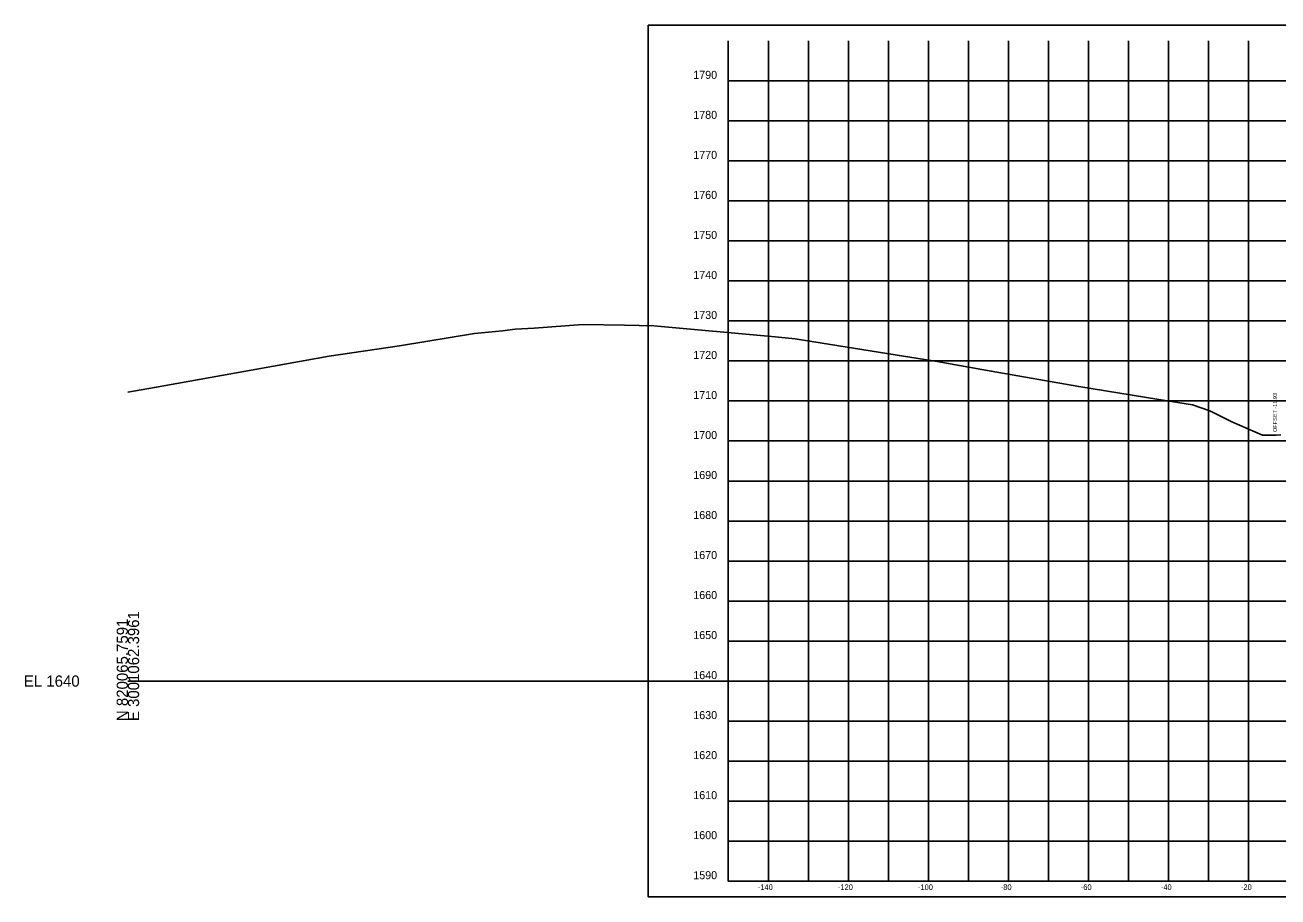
# Model space of a CAD drawing. Extents: x -26 to 603, y -61 to 1770.
# Drawn here: x -25.7 to 287.3, y 1446.1 to 1663.9 of the extents above; entities that cross this region are included whole.
import ezdxf

# ---------------------------------------------------------------- set-up
doc = ezdxf.new("R2010")
doc.units = 0
for name, color, linetype in [('DESIGN - SHEET - Corner Text', 7, 'Continuous'), ('DESIGN - SHEET - Light Grid', 7, 'Continuous'), ('DESIGN - SHEET - Linework', 7, 'Continuous'), ('DESIGN - SHEET - Plot Shape', 7, 'Continuous'), ('DESIGN - TYPICAL - Slope Tie Text', 7, 'Continuous'), ('SURVEY - GROUND - Top of Ground', 7, 'Continuous')]:
    doc.layers.add(name, color=color, linetype=linetype)

msp = doc.modelspace()

# ---------------------------------------------------------------- linework, layer by layer
at = {"layer": 'DESIGN - SHEET - Light Grid'}
msp.add_line((0, 1500), (300, 1500), dxfattribs=at)
at = {"layer": 'DESIGN - SHEET - Linework'}
for p, q in [((160, 1450), (160, 1660)), ((170, 1450), (170, 1660)), ((180, 1450), (180, 1660)), ((190, 1450), (190, 1660)), ((200, 1450), (200, 1660)), ((210, 1450), (210, 1660)), ((220, 1450), (220, 1660)), ((230, 1450), (230, 1660)), ((240, 1450), (240, 1660)), ((250, 1450), (250, 1660)), ((260, 1450), (260, 1660)), ((270, 1450), (270, 1660)), ((280, 1450), (280, 1660)), ((150, 1650), (450, 1650)), ((150, 1640), (450, 1640)), ((150, 1630), (450, 1630)), ((150, 1620), (450, 1620)), ((150, 1610), (450, 1610)), ((150, 1600), (450, 1600)), ((150, 1590), (450, 1590)), ((150, 1580), (450, 1580)), ((150, 1570), (450, 1570)), ((150, 1560), (450, 1560)), ((150, 1550), (450, 1550)), ((150, 1540), (450, 1540)), ((150, 1530), (450, 1530)), ((150, 1520), (450, 1520)), ((150, 1510), (450, 1510)), ((150, 1500), (450, 1500)), ((150, 1490), (450, 1490)), ((150, 1480), (450, 1480)), ((150, 1470), (450, 1470)), ((150, 1460), (450, 1460))]:
    msp.add_line(p, q, dxfattribs=at)
msp.add_lwpolyline([(150, 1660), (150, 1450), (450, 1450), (450, 1660)], dxfattribs=at)
at = {"layer": 'DESIGN - SHEET - Plot Shape'}
msp.add_lwpolyline([(130, 1663.94), (470, 1663.94), (470, 1446.06), (130, 1446.06)], close=True, dxfattribs=at)
at = {"layer": 'SURVEY - GROUND - Top of Ground'}
msp.add_lwpolyline([(0, 1572.22), (6.63, 1573.4), (28.94, 1577.36), (50.3, 1581.17), (67.86, 1583.81), (86.57, 1586.86), (93.56, 1587.55), (96.77, 1587.91), (101.47, 1588.18), (113.69, 1589.1), (124.1, 1588.93), (131.36, 1588.79), (161.7, 1585.99), (166.73, 1585.5), (192.17, 1581.46), (202.15, 1579.87), (215.69, 1577.49), (237.56, 1573.59), (257.54, 1570.4), (265.99, 1569.07), (270.3, 1567.51), (275.78, 1564.79), (283.42, 1561.44), (286.84, 1561.44), (288.07, 1561.5)], dxfattribs=at)

# ---------------------------------------------------------------- texts
at = {"layer": 'DESIGN - SHEET - Corner Text'}
for s, height, p in [('1790', 2, (141.25, 1650.5)), ('1780', 2, (141.25, 1640.5)), ('1770', 2, (141.25, 1630.5)), ('1760', 2, (141.25, 1620.5)), ('1750', 2, (141.25, 1610.5)), ('1740', 2, (141.25, 1600.5)), ('1730', 2, (141.25, 1590.5)), ('1720', 2, (141.25, 1580.5)), ('1710', 2, (141.25, 1570.5)), ('1700', 2, (141.25, 1560.5)), ('1690', 2, (141.25, 1550.5)), ('1680', 2, (141.25, 1540.5)), ('1670', 2, (141.25, 1530.5)), ('1660', 2, (141.25, 1520.5)), ('1650', 2, (141.25, 1510.5)), ('1640', 2, (141.25, 1500.5)), ('1630', 2, (141.25, 1490.5)), ('1620', 2, (141.25, 1480.5)), ('1610', 2, (141.25, 1470.5)), ('1600', 2, (141.25, 1460.5)), ('1590', 2, (141.25, 1450.5)), ('-140', 1.4, (157.37, 1447.8)), ('-120', 1.4, (177.37, 1447.8)), ('-100', 1.4, (197.37, 1447.8)), ('-80', 1.4, (218.06, 1447.8)), ('-60', 1.4, (238.06, 1447.8)), ('-40', 1.4, (258.06, 1447.8)), ('-20', 1.4, (278.06, 1447.8))]:
    msp.add_text(s, height=height, dxfattribs=at).set_placement(p)
at = {"layer": 'DESIGN - SHEET - Light Grid'}
for s, p in [('N 820065.7591', (0, 1490)), ('E 3001062.3961', (2.8, 1490))]:
    msp.add_text(s, height=2.8, rotation=90, dxfattribs=at).set_placement(p)
msp.add_text('EL 1640', height=2.8, dxfattribs=at).set_placement((-26, 1498.6))
at = {"layer": 'DESIGN - TYPICAL - Slope Tie Text'}
msp.add_text('OFFSET -11.93', height=1, rotation=90, dxfattribs=at).set_placement((287.07, 1562.25))

doc.saveas('drawing.dxf')
